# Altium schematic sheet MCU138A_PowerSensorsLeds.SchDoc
size 431 x 279 mm; Date: Not shown in title block; ApprovedBy: Not shown in title block; CheckedBy: Not shown in title block; Author: Not shown in title block; CompanyName: Not shown in title block; DrawnBy: Jonathan Cohen; Engineer: Not shown in title block; Organization: Not shown in title block; Address1: Not shown in title block; Address2: Not shown in title block; Address3: Not shown in title block; Address4: Not shown in title block; DocumentNumber: 2; Revision: Use project parameter SCH_Rev; SheetNumber: 2; SheetTotal: 3; PageSetup: Record=PageOptions¦CenterHorizontal=True¦CenterVertical=True¦PrintScale=1.00¦XCorrection=1.00¦YCorrection=1.00¦PrintKind=0¦BorderSize=5000000¦LeftOffset=0¦BottomOffset=0¦Orientation=2¦PaperLength=1000¦PaperWidth=1000¦Scale=100¦PaperSource=15¦PrintQuality=600¦MediaType=1¦DitherType=10¦PaperKind=Letter¦PrintScaleMode=1
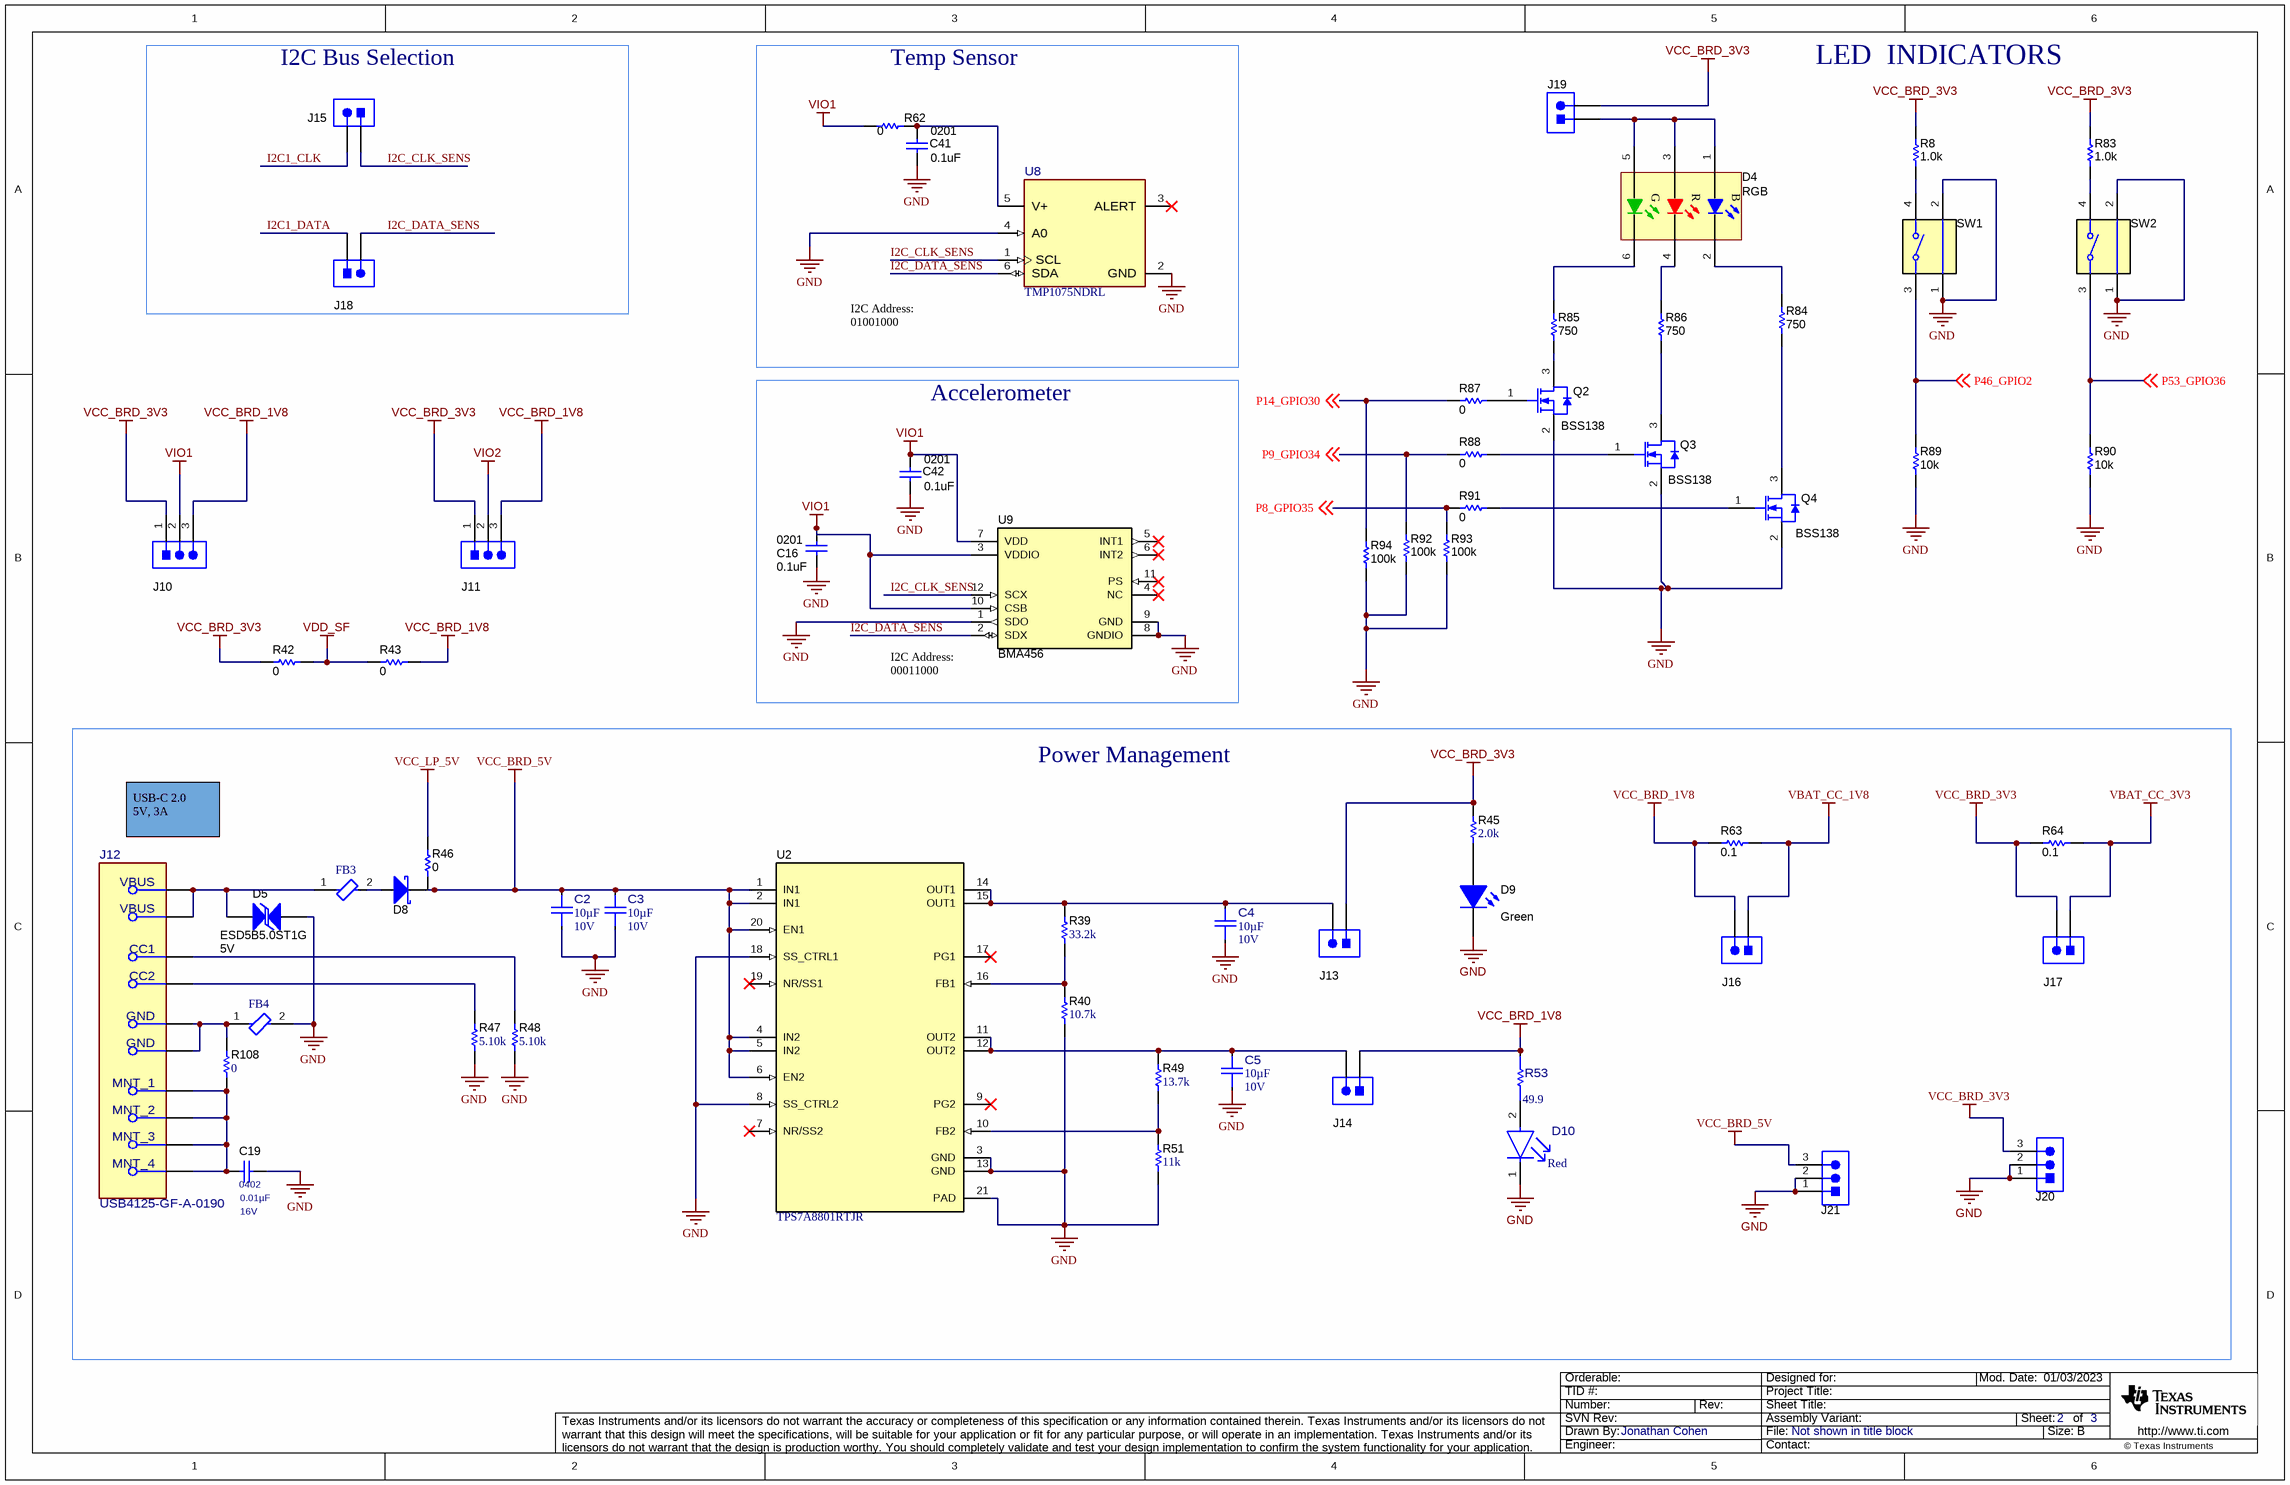
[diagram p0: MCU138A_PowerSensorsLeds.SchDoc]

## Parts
C2  Cap_F: 10µF  VDC_V: 10V  [FP-GRM188Z71A106MA73J_0603-MFG]  (hidden comment: GRM188Z71A106MA73J)
C3  Cap_F: 10µF  VDC_V: 10V  [FP-GRM188Z71A106MA73J_0603-MFG]  (hidden comment: GRM188Z71A106MA73J)
C4  Cap_F: 10µF  VDC_V: 10V  [FP-GRM188Z71A106MA73J_0603-MFG]  (hidden comment: GRM188Z71A106MA73J)
C5  Cap_F: 10µF  VDC_V: 10V  [FP-GRM188Z71A106MA73J_0603-MFG]  (hidden comment: GRM188Z71A106MA73J)
C16  ValueDisplayed: 0.1uF  [0201]  (hidden comment: GRM033C71A104KE14D)
C19  VDC_V: 16V  ValueDisplayed: 0.01µF  [0402]  (hidden comment: C0402C103K4RACTU)
C41  ValueDisplayed: 0.1uF  [0201]  (hidden comment: GRM033C71A104KE14D)
C42  ValueDisplayed: 0.1uF  [0201]  (hidden comment: GRM033C71A104KE14D)
D4  Color: RGB  [EAST1616_RGB]  (hidden comment: CMP-0003017-2)
D5  ESD5B5.0ST1G  value 5V  [SOD-523F_Bi]
D8  MBR130T1G  [SOD-123]  (value not drawn)
D9  value Green  [WL-SMCW_GREEN]  (hidden comment: CMP-0002905-1)
D10  Color: Red  [FP-CTL0603FRD1T_0603-MFG]  (hidden comment: CTL0603FRD1T)
FB3  BLM18PG471SN1D  [FP-BLM18-0_15-t0_8-MFG]  (value not drawn)
FB4  BLM18PG471SN1D  [FP-BLM18-0_15-t0_8-MFG]  (value not drawn)
J10  CMP-0054796-1  [WURTH_61300311121]  (value not drawn)
J11  CMP-0054796-1  [WURTH_61300311121]  (value not drawn)
J12  USB4125-GF-A-0190  [FP-USB4125-GF-A-0190_CONN_USB-MFG]
J13  61300211121  [WURTH_61300211121]  (value not drawn)
J14  61300211121  [WURTH_61300211121]  (value not drawn)
J15  61300211121  [WURTH_61300211121]  (value not drawn)
J16  61300211121  [WURTH_61300211121]  (value not drawn)
J17  61300211121  [WURTH_61300211121]  (value not drawn)
J18  61300211121  [WURTH_61300211121]  (value not drawn)
J19  CMP-0054794-1  [WURTH_61300211121]  (value not drawn)
J20  CMP-0054796-1  [WURTH_61300311121]  (value not drawn)
J21  CMP-0054796-1  [WURTH_61300311121]  (value not drawn)
Q2  PartNumber: BSS138  [SOT-23]  (hidden comment: CMP-0000755-1)
Q3  PartNumber: BSS138  [SOT-23]  (hidden comment: CMP-0000755-1)
Q4  PartNumber: BSS138  [SOT-23]  (hidden comment: CMP-0000755-1)
R8  ValueDisplayed: 1.0k  [0402]  (hidden comment: CMP-0026852-3)
R39  ValueDisplayed: 33.2k  [0201]  (hidden comment: RC0201FR-0733K2L)
R40  ValueDisplayed: 10.7k  [0201]  (hidden comment: RC0201FR-0710K7L)
R42  ValueDisplayed: 0  [0402S]  (hidden comment: CMP-0026992-2)
R43  ValueDisplayed: 0  [0402S]  (hidden comment: CMP-0026992-2)
R45  ValueDisplayed: 2.0k  [0201]  (hidden comment: RC0201JR-7D2KL)
R46  ValueDisplayed: 0  [0402S]  (hidden comment: CMP-0026992-2)
R47  ValueDisplayed: 5.10k  [0201]  (hidden comment: RC0201FR-075K1L)
R48  ValueDisplayed: 5.10k  [0201]  (hidden comment: RC0201FR-075K1L)
R49  ValueDisplayed: 13.7k  [0201]  (hidden comment: RC0201FR-7D13K7L)
R51  ValueDisplayed: 11k  [0201]  (hidden comment: RC0201JR-0711KL)
R53  value 49.9  [FP-ERJ-1GNF49R9C_0201-MFG]  (hidden comment: ERJ-1GNF49R9C)
R62  ValueDisplayed: 0  [0402S]  (hidden comment: CMP-0026992-2)
R63  ValueDisplayed: 0.1  [0805_HV]  (hidden comment: CMP-0021515-2)
R64  ValueDisplayed: 0.1  [0805_HV]  (hidden comment: CMP-0021515-2)
R83  ValueDisplayed: 1.0k  [0402]  (hidden comment: CMP-0026852-3)
R84  ValueDisplayed: 750  [0603]  (hidden comment: CMP-0025939-3)
R85  ValueDisplayed: 750  [0603]  (hidden comment: CMP-0025939-3)
R86  ValueDisplayed: 750  [0603]  (hidden comment: CMP-0025939-3)
R87  ValueDisplayed: 0  [0402]  (hidden comment: CMP-0026992-2)
R88  ValueDisplayed: 0  [0402]  (hidden comment: CMP-0026992-2)
R89  ValueDisplayed: 10k  [0402]  (hidden comment: CMP-0026825-5)
R90  ValueDisplayed: 10k  [0402]  (hidden comment: CMP-0026825-5)
R91  ValueDisplayed: 0  [0402]  (hidden comment: CMP-0026992-2)
R92  ValueDisplayed: 100k  [0402]  (hidden comment: CMP-0026823-3)
R93  ValueDisplayed: 100k  [0402]  (hidden comment: CMP-0026823-3)
R94  ValueDisplayed: 100k  [0402]  (hidden comment: CMP-0026823-3)
R108  ValueDisplayed: 0  [0201]  (hidden comment: CRCW02010000Z0ED)
SW1  CMP-0002328-1  [SW_1188E]  (value not drawn)
SW2  CMP-0002328-1  [SW_1188E]  (value not drawn)
U2  TPS7A8801RTJR  [RTJ0020D]
U8  TMP1075NDRL  [DRL0006A-MFG]
U9  BMA456  [12LGA]

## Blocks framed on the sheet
I2C Bus Selection: J15 J18
Temp Sensor: C41 R62 U8
Accelerometer: C16 C42 U9
Power Management: C2-C5 C19 D5 D8-D10 FB3 FB4 J12-J14 J16 J17 J20 J21 R39 R40 R45-R49 R51 R53 R63 R64 R108 U2

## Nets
GND: C2.1 C3.1 C4.1 C5.1 C16.2 C19.2 C41.2 C42.2 D5.2 D9.1(K) D10.1(CATHODE) FB4.2 J20.1 J20.2 J21.1 J21.2 Q2.2(S) Q3.2(S) Q4.2(S) R40.1 R47.1 R48.2 R51.1 R89.2 R90.2 R92.2 R93.2 R94.2 SW1.1 SW1.2 SW2.1 SW2.2 U2.3(GND) U2.8(SS_CTRL2) U2.13(GND) U2.18(SS_CTRL1) U2.21(PAD) U8.2(GND) U8.4(A0) U9.1(SDO) U9.8(GNDIO) U9.9(GND)
VBAT_CC_1V8: J16.1 R63.2
VBAT_CC_3V3: J17.1 R64.2
VCC_BRD_1V8: J10.3 J11.3 J14.1 J16.2 R43.1 R53.2 R63.1
VCC_BRD_3V3: J10.1 J11.1 J13.1 J17.2 J19.2 J20.3 R8.1 R42.2 R45.2 R64.1 R83.1
VCC_BRD_5V: C2.2 C3.2 D8.1(K) J21.3 R46.1 U2.1(IN1) U2.2(IN1) U2.4(IN2) U2.5(IN2) U2.6(EN2) U2.20(EN1)
VCC_LP_5V: R46.2
VDD_SF: R42.1 R43.2
VIO1: C16.1 C42.1 J10.2 R62.2 U9.3(VDDIO) U9.7(VDD) U9.10(CSB)
VIO2: J11.2
I2C1_CLK: J15.2
I2C1_DATA: J18.1
I2C_CLK_SENS: J15.1 U8.1(SCL) U9.12(SCX)
I2C_DATA_SENS: J18.2 U8.6(SDA) U9.2(SDX)
P8_GPIO35: R91.1 R93.1 ; off-sheet P8_GPIO35
P9_GPIO34: R88.1 R92.1 ; off-sheet P9_GPIO34
P14_GPIO30: R87.1 R94.1 ; off-sheet P14_GPIO30
P46_GPIO2: R89.1 SW1.3 ; off-sheet P46_GPIO2
P53_GPIO36: R90.1 SW2.3 ; off-sheet P53_GPIO36
NetC4_2: C4.2 J13.2 R39.2 U2.14(OUT1) U2.15(OUT1)
NetC5_2: C5.2 J14.2 R49.2 U2.11(OUT2) U2.12(OUT2)
NetC19_1: C19.1 J12.1(MNT_1) J12.2(MNT_2) J12.3(MNT_3) J12.4(MNT_4) R108.1
NetC41_1: C41.1 R62.1 U8.5(V+)
NetD4_1: D4.1(A) D4.3(A) D4.5(A) J19.1
NetD4_2: D4.2(K) R84.2
NetD4_4: D4.4(K) R86.2
NetD4_6: D4.6(K) R85.2
NetD5_1: D5.1 FB3.1 J12.A9(VBUS) J12.B9(VBUS)
NetD8_2: D8.2(A) FB3.2
NetD9_2: D9.2(A) R45.1
NetD10_2: D10.2(ANODE) R53.1
NetFB4_1: FB4.1 J12.A12(GND) J12.B12(GND) R108.2
NetJ12_A5: J12.A5(CC1) R48.1
NetJ12_B5: J12.B5(CC2) R47.2
NetQ2_1: Q2.1(G) R87.2
NetQ2_3: Q2.3(D) R85.1
NetQ3_1: Q3.1(G) R88.2
NetQ3_3: Q3.3(D) R86.1
NetQ4_1: Q4.1(G) R91.2
NetQ4_3: Q4.3(D) R84.1
NetR8_2: R8.2 SW1.4
NetR39_1: R39.1 R40.2 U2.16(FB1)
NetR49_1: R49.1 R51.2 U2.10(FB2)
NetR83_2: R83.2 SW2.4

Not connected (* = marked no-connect by the designer): U2 7(NR/SS2)* 9(PG2)* 17(PG1)* 19(NR/SS1)*; U8 3(ALERT)*; U9 4(NC)* 5(INT1)* 6(INT2)* 11(PS)*

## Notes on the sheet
- LED  INDICATORS
- I2C Address:
  01001000
- (near U9) I2C Address:
  00011000
- USB-C 2.0
  5V, 3A

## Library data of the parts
C2-C5 = CMP-0092206-1: Chip Multilayer Ceramic Capacitors for General Purpose, 0603, 10uF, X7R, 15%, 20%, 10V; Manufacturer: Murata; Value: 10µF; AEC Qualified: No; SizeZ_mm: 1mm
C16 C41 C42 = CMP-0064969-1: CAP, CERM, 0.1 uF, 10 V,+/- 10%, X7S, 0201; Manufacturer: MuRata; TaMin_C: -55°C; Polarized: N; SizeAreaWB_mm2: 2.08; Value1: Unknown; U/M: EA; Value: 0.1uF; TaMax_C: 125°C; SizeZ_mm: 0.26; SizeX_mm: 0.6; SizeY_mm: 0.3; Value2: 10V; SizeArea_mm2: 0.18; Cap_F: 100nF; AEC Category: Q200
C19 = CMP-0078218-1: CAP, CERM, 0.01 µF, 16 V,+/- 10%, X7R, 0402; Manufacturer: Kemet; TaMin_C: -55°C; Polarized: N; Green_Lifecycle: Active; SizeAreaWB_mm2: 3; Green_REACh: Passed; U/M: EA; Value: 0.01uF; TaMax_C: 125°C; SizeZ_mm: 0.6; SizeX_mm: 1; SizeY_mm: 0.5; Cap_F: 10nF; AEC Category: Q200
D4 = CMP-0003017-2: LED, Rgb, SMD; PartNumber: EAST1616RGBA8; Manufacturer: Everlight; Alternate PartNumber: 19-337-R6GHBHC-C02-2T; Type: InGaN; Vf_V: 3.7V; Io_A: 25mA; Vr_V: 5V; Ir_A: 50µA; Tjmax_C: 85°C; Value1: W; Angle: 120; SizeAreaWB_mm2: 6.76; SizeArea_mm2: 2.56; SizeX_mm: 1.6; SizeZ_mm: 0.45; U/M: EA
D5 = CMP-0074747-2: Diode, TVS, Bi, 5 V, SOD-523F; Manufacturer: ON Semiconductor; SizeArea_mm2: 1.28; SizeAreaWB_mm2: 4.68; SizeZ_mm: 0.7; Value1: 50W; SizeY_mm: 0.8; AEC Qualified: N; SizeX_mm: 1.6; AEC Category: Q101
D8 = CMP-0028547-1: Diode, Schottky, 30 V, 1 A, SOD-123; Manufacturer: ON Semiconductor; Io_A: 1A; Green_Lifecycle: Active; SizeAreaWB_mm2: 13.095; Vr_V: 30V; Green_REACh: Passed; TJmax_C: 125°C; U/M: EA; Value: 30V; SizeZ_mm: 1.35; SizeX_mm: 3.85; SizeY_mm: 1.7; Vf_V: 4.7dV; Value2: 0.47V; SizeArea_mm2: 6.545; AEC Category: Q101; RJC_CperW: 108
D9 = CMP-0002905-1: LED, Green, SMD; Manufacturer: Wurth Elektronik; PartNumber: 150060GS75000; Alternate Manufacturer: Everlight; Alternate PartNumber: 19-217/GHC-YR1S2/3T; Type: InGaN; Vf_V: 3.2V; Io_A: 20mA; Tjmax_C: 85°C; Value1: W; Angle: 140; U/M: EA
D10 = CMP-0092006-1: Red 630nm LED Indication - Discrete 1.5V 0603 (1608 Metric); Manufacturer: Venkel; Led Orientation: Top View; Vf_V: 2.4V; TaMin_C: -40°C; Vr_V: 5V; LambdaP: 640nm; Power_TotalModule: 60mW; TaMax_C: +85°C; Forward Current: 20mA; Angle: 130°; Luminous Intensity: 80mcd; SizeZ_mm: 0.5mm; AEC Qualified: No
FB3 FB4 = CMP-0686-00587-3: Chip Ferrite Bead, 0603, 470Ω @ 100MHz, 0.2Ω, 25%, 1A; DC Resistance (DCR): 200mR; Number of Circuits: 1; Material: Steel; Impedance: 470R
J10 J11 J20 J21 = CMP-0054796-1: Header, 2.54 mm, 3x1, Gold, TH; PartNumber: 61300311121; Manufacturer: Wurth Elektronik; Alternate Manufacturer: ----; CNHeader: TRUE; Green_Lifecycle: Active; Green_REACh: Passed; CT: FALSE
J12 = CMP-0094557-1: 24 (6+18 Dummy) Position USB-C (USB TYPE-C) USB 2.0 Receptacle Connector; Manufacturer: GCT; Usb Standard: USB 2.0; Conn Orientation: Horizontal; SizeZ_mm: 3.51mm; ContactFinish: Gold; Current_A: 3A; Voltage_V: 20V; Is Female: yes; Shrouded: true; AEC Qualified: No
J13-J18 = CMP-0054794-1: Header, 2.54 mm, 2x1, Gold, TH; Manufacturer: Wurth Elektronik; CNHeader: TRUE; Green_Lifecycle: Active; Green_REACh: Passed; CT: FALSE
J19 = CMP-0054794-1: Header, 2.54 mm, 2x1, Gold, TH; PartNumber: 61300211121; Manufacturer: Wurth Elektronik; Alternate Manufacturer: ----; CNHeader: TRUE; Green_Lifecycle: Active; Green_REACh: Passed; CT: FALSE
Q2-Q4 = CMP-0000755-1: MOSFET, N-CH, 50 V, 0.22 A, SOT-23; Manufacturer: Fairchild Semiconductor; Alternate Manufacturer: ON; Alternate PartNumber: BSS138LT1G; U/M: EA; ChType: N; Value: 50V; Rdson45_ohm: 6; Value2: 1.7 nC; QgTyp_nC: 1.7; Vgs_V: 20V; IdsMax_A: 2.2dA; SizeAreaWB_mm2: 14; SizeArea_mm2: 7.5; SizeX_mm: 2.5; SizeY_mm: 3; SizeZ_mm: 1.1; AEC Category: Q101
R8 R83 = CMP-0026852-3: RES, 1.0 k, 5%, 0.063 W, AEC-Q200 Grade 0, 0402; PartNumber: CRCW04021K00JNED; Manufacturer: Vishay-Dale; Alternate Manufacturer: YAGEO; Alternate PartNumber: RC0402JR-071KL; Value: 1.0k; Res_ohm: 1k; Value_Code: 1k00; Power_W: 63mW; Value2: 0.063W; VDC_V: 50V; TempCo: 200 ppm/C; EIA_Code: E24; SizeX_mm: 1; SizeY_mm: 0.5; SizeZ_mm: 0.6; AEC Qualified: Y; AEC Category: Q200; AEC Grade: 0
R39 = CMP-0027612-1: RES, 33.2 k, 1%, 0.05 W, 0201; Manufacturer: Yageo America; Power_W: 50mW; TempCo: 200 ppm/C; Value_Code: 33k2; U/M: EA; Value: 33.2k; EIA_Code: E96; SizeX_mm: 0.6; SizeY_mm: 0.3; SizeZ_mm: 0.26; Value2: 0.05W; SizeArea_mm2: 0.18; AEC Qualified: N; VDC_V: 25V; AEC Category: Q200
R40 = CMP-0027303-2: RES, 10.7 k, 1%, 0.05 W, 0201; Manufacturer: Yageo America; Power_W: 50mW; TempCo: 200 ppm/C; Value_Code: 10k7; U/M: EA; Value: 10.7k; EIA_Code: E96; SizeX_mm: 0.6; SizeY_mm: 0.3; SizeZ_mm: 0.26; Value2: 0.05W; SizeArea_mm2: 0.18; AEC Qualified: N; VDC_V: 25V; AEC Category: Q200
R42 R43 R46 R62 = CMP-0026992-2: RES, 0, 5%, 0.063 W, 0402; PartNumber: ERJ-2GE0R00X; Manufacturer: Panasonic; Alternate Manufacturer: YAGEO; Alternate PartNumber: RC0402JR-070RL; CompType: Resistor; Value: 0; Value_Code: 0000; Power_W: 63mW; Value2: 0.063W; VDC_V: 50V; TempCo: 600 ppm/C; SizeArea_mm2: 0.5; SizeX_mm: 1; SizeZ_mm: 0.6; EIA_Code: E24; U/M: EA; AEC Category: Q200
R45 = CMP-0027219-1: RES, 2.0 k, 5%, 0.05 W, 0201; Manufacturer: Yageo America; Power_W: 50mW; TempCo: 200 ppm/C; Value_Code: 2k00; U/M: EA; Value: 2.0k; EIA_Code: E24; SizeX_mm: 0.6; SizeY_mm: 0.3; SizeZ_mm: 0.26; Value2: 0.05W; SizeArea_mm2: 0.18; AEC Qualified: N; VDC_V: 25V; AEC Category: Q200; Res_ohm: 2k
R47 R48 = CMP-0027789-1: RES, 5.10 k, 1%, 0.05 W, 0201; Manufacturer: Yageo America; Power_W: 50mW; TempCo: 200 ppm/C; Value_Code: 5k10; U/M: EA; Value: 5.10k; Res_ohm: 5.1k; SizeX_mm: 0.6; SizeY_mm: 0.3; SizeZ_mm: 0.26; Value2: 0.05W; SizeArea_mm2: 0.18; AEC Qualified: N; VDC_V: 25V; AEC Category: Q200
R49 = CMP-0027957-1: RES, 13.7 k, 1%, 0.05 W, 0201; Manufacturer: Yageo America; Power_W: 50mW; TempCo: 200 ppm/C; Value_Code: 13k7; U/M: EA; Value: 13.7k; EIA_Code: E96; SizeX_mm: 0.6; SizeY_mm: 0.3; SizeZ_mm: 0.26; Value2: 0.05W; SizeArea_mm2: 0.18; AEC Qualified: N; VDC_V: 25V; AEC Category: Q200
R51 = CMP-0027024-1: RES, 11 k, 5%, 0.05 W, 0201; Manufacturer: Yageo America; Power_W: 50mW; TempCo: 200 ppm/C; Value_Code: 11k0; U/M: EA; Value: 11k; EIA_Code: E24; SizeX_mm: 0.6; SizeY_mm: 0.3; SizeZ_mm: 0.26; Value2: 0.05W; SizeArea_mm2: 0.18; AEC Qualified: N; VDC_V: 25V; AEC Category: Q200
R53 = CMP-0097243-1: 49.9 Ohms ±1% 0.05W, 1/20W Chip Resistor 0201 (0603 Metric) Automotive AEC-Q200 Thick Film; Manufacturer: Panasonic Electronic Components; AEC Qualified: Yes; Power_W: 50mW; AEC Grade: Grade 1; VDC_V: 25V; SizeZ_mm: 0.26mm; TempCo: 200ppm/°C
R63 R64 = CMP-0021515-2: RES, 0.1, 1%, 0.25 W, 0805; PartNumber: CRM0805-FX-R100ELF; Manufacturer: Bourns; Alternate Manufacturer: ----; CompType: Resistor; Value: 0.1; Res_ohm: 1d; Value_Code: R100; Power_W: 250mW; Value2: 0.25W; VDC_V: 0V; TempCo: 150 ppm/C; EIA_Code: E96; U/M: EA; SizeX_mm: 2; SizeY_mm: 1.25; SizeZ_mm: 1.45; SizeArea_mm2: 2.5; AEC Category: Q200
R84-R86 = CMP-0025939-3: RES, 750, 5%, 0.1 W, 0603; PartNumber: RC0603JR-07750RL; Manufacturer: Yageo America; Alternate Manufacturer: ----; Value: 750; Value_Code: 750R; Power_W: 100mW; Value2: 0.1W; VDC_V: 50V; TempCo: 100 ppm/C; SizeArea_mm2: 1.28; SizeX_mm: 1.6; SizeY_mm: 0.8; SizeZ_mm: 1; EIA_Code: E24; U/M: EA; AEC Category: Q200
R87 R88 R91 = CMP-0026992-2: RES, 0, 5%, 0.063 W, 0402; PartNumber: ERJ-2GE0R00X; Manufacturer: Panasonic; Alternate Manufacturer: YAGEO; Alternate PartNumber: RC0402JR-070RL; Value: 0; Value_Code: 0000; Power_W: 63mW; Value2: 0.063W; VDC_V: 50V; TempCo: 600 ppm/C; EIA_Code: E24; U/M: EA; SizeX_mm: 1; SizeY_mm: 0.5; SizeZ_mm: 0.6; AEC Category: Q200
R89 R90 = CMP-0026825-5: RES, 10 k, 5%, 0.063 W, AEC-Q200 Grade 0, 0402; PartNumber: CRCW040210K0JNED; Manufacturer: Vishay-Dale; Alternate Manufacturer: YAGEO; Alternate PartNumber: RC0402JR-0710KL; Value: 10k; Value_Code: 10k0; Power_W: 63mW; Value2: 0.063W; VDC_V: 50V; TempCo: 200 ppm/C; EIA_Code: E24; SizeX_mm: 1; SizeY_mm: 0.5; SizeZ_mm: 0.6; AEC Qualified: Y; AEC Category: Q200; AEC Grade: 0
R92-R94 = CMP-0026823-3: RES, 100 k, 5%, 0.063 W, AEC-Q200 Grade 0, 0402; PartNumber: CRCW0402100KJNED; Manufacturer: Vishay-Dale; Alternate Manufacturer: YAGEO; Alternate PartNumber: RC0402JR-07100KL; Value: 100k; Power_W: 63mW; Value2: 0.063W; VDC_V: 50V; TempCo: 200 ppm/C; EIA_Code: E24; SizeArea_mm2: 0.5; SizeX_mm: 1; SizeZ_mm: 0.6; AEC Category: Q200; AEC Qualified: Y; AEC Grade: 0
R108 = CMP-0027008-4: RES, 0, 5%, 0.05 W, 0201; Manufacturer: Vishay-Dale; Power_W: 50mW; TempCo: ppm/C; Value_Code: 0000; Value: 0; EIA_Code: E24; SizeX_mm: 0.6; SizeY_mm: 0.3; SizeZ_mm: 0.26; Value2: 0.05W; SizeArea_mm2: 0.18; AEC Qualified: N; AEC Category: Q200
SW1 SW2 = CMP-0002328-1: Switch, SPST, 0.05 A, 12 VDC, SMD; PartNumber: 1188E-1K2-V-TR; Manufacturer: Diptronics; Alternate Manufacturer: ----; VDC_V: 12V; PositionCount: 1; CurrentRating_mA: 50A; SizeAreaWB_mm2: 53.9; SizeArea_mm2: 27.3; SizeX_mm: 7.8; SizeY_mm: 3.5
U2 = CMP-0073732-3: Dual 1A Low-Noise (3.8μVRMS) LDO Voltage Regulator, RTJ0020D (WQFN-20); Alternate PartNumber: TPS7A8801RTJT; Alternate Manufacturer: Texas Instruments; Green_Lifecycle: Active; SizeAreaWB_mm2: 25.0; Green_REACh: Passed; SizeZ_mm: 0.8; SizeX_mm: 4.0; SizeArea_mm2: 16.0; CompType: IC; AEC Category: Q200; AEC Qualified: N; Rating: Catalog
U8 = CMP-0092110-1: Temperature Sensor With I 2C and SMBus Interface in Industry Standard LM75 Form Factor and Pinout; Manufacturer: Texas Instruments; Resolution: 12bits; Sensor Output: I2C,SMBus; TJmax_C: +150°C; SizeZ_mm: 0.6mm; Operating Supply Current: 4-52uA; Interface: I2C,2-Wire,SMBus; Min Supply Voltage: 1.7V; AEC Qualified: No; TaMax_C: +125°C; Standoff Height: 0mm; TaMin_C: -55°C; Max Supply Voltage: 5.5V
U9 = CMP-0004812-1: 14 Bit, Digital, Triaxial Acceleration Sensor with Intelligent On-Chip Motion-Triggered Interrupt Controller, 12LGA; Manufacturer: Bosch Solar Energy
